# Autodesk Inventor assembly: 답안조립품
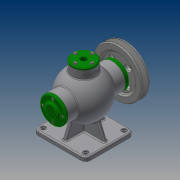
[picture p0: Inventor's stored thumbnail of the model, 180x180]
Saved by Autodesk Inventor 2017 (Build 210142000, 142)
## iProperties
Part Number: 답안조립품
Material: 일반
Document SubType Name: Assembly
Designer: 13
Author: 13
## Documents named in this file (18)
- C:\Users\13\Desktop\480414V1002\답안조립품.iam
- C:\Users\13\Desktop\480414V1002\본체.ipt
- C:\Users\13\Desktop\480414V1002\뒤커버.ipt
- C:\Users\13\Desktop\480414V1002\앞커버.ipt
- C:\Users\13\Desktop\480414V1002\오일 실 15 30 7.ipt
- C:\Users\13\Desktop\480414V1002\베어링 6202.ipt
- 베어링 6202.ipt
- C:\Users\13\Desktop\480414V1002\멈춤링 15x1.ipt
- C:\Users\13\Desktop\480414V1002\편심축.ipt
- C:\Users\13\Desktop\480414V1002\부시.ipt
- C:\Users\13\Desktop\480414V1002\멈춤링 35x1.6.ipt
- 멈춤링 35x1.6.ipt
- C:\Users\13\Desktop\480414V1002\키 4x4x12.ipt
- C:\Users\13\Desktop\480414V1002\V-벨트풀리.ipt
- C:\Users\13\Desktop\480414V1002\너트 M8.ipt
- C:\Users\13\Desktop\480414V1002\상부커버.ipt
- C:\Users\13\Desktop\480414V1002\볼트 M4x16.ipt
- C:\Users\13\Desktop\480414V1002\볼트 M4x12.ipt
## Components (1 placed, 1 different names)
1. V-벨트풀리:1 — 플러쉬:1
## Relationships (1: Flush 1)
- 플러쉬:1 [Flush]: V-벨트풀리:1
